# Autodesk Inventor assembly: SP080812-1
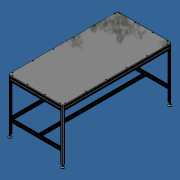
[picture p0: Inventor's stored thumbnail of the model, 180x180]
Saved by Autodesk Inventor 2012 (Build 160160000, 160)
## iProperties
Created: 2012-08
Part Number: SP080812-1
Document SubType Name: Assembly
Designer: Administrator
Author: Administrator
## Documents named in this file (10)
- C:\Andys Backup Data\ANDY'S INVENTOR\INVENTOR LIBRARIES\ASSEMBLY LIBRARY\30 SERIES\TABLES BASES CARTS\SP080812-1 30R90 TABLE\SP080812-1 30R90 TABLE.iam
- C:\Andys Backup Data\ANDY'S INVENTOR\INVENTOR LIBRARIES\ASSEMBLY LIBRARY\30 SERIES\TABLES BASES CARTS\SP080812-1 30R90 TABLE\SP080812-1-1 30R90 LEG.ipt
- C:\Andys Backup Data\ANDY'S INVENTOR\INVENTOR LIBRARIES\PARTS LIBRARY\FEET WHEELS FLOOR FASTENING SUPPORTS\21.1871 LEVELING FOOT M8 45mm BASE.iam
- C:\Andys Backup Data\ANDY'S INVENTOR\INVENTOR LIBRARIES\ASSEMBLY LIBRARY\30 SERIES\TABLES BASES CARTS\SP080812-1 30R90 TABLE\SP080812-1-2 30X60 HORI WIDTH.ipt
- C:\Andys Backup Data\ANDY'S INVENTOR\INVENTOR LIBRARIES\ASSEMBLY LIBRARY\30 SERIES\TABLES BASES CARTS\SP080812-1 30R90 TABLE\SP080812-1-3 30X60 DEPTH HORI.ipt
- C:\Andys Backup Data\ANDY'S INVENTOR\INVENTOR LIBRARIES\ASSEMBLY LIBRARY\30 SERIES\TABLES BASES CARTS\SP080812-1 30R90 TABLE\SP080812-1-4 30X30 DEPTH HORI.ipt
- C:\Andys Backup Data\ANDY'S INVENTOR\INVENTOR LIBRARIES\ASSEMBLY LIBRARY\30 SERIES\TABLES BASES CARTS\SP080812-1 30R90 TABLE\SP080812-1-5 30X30 WIDTH HORI.ipt
- C:\Andys Backup Data\ANDY'S INVENTOR\INVENTOR LIBRARIES\ASSEMBLY LIBRARY\30 SERIES\TABLES BASES CARTS\SP080812-1 30R90 TABLE\SP080812-1-6 TABLE TOP.ipt
- C:\Andys Backup Data\ANDY'S INVENTOR\INVENTOR LIBRARIES\PARTS LIBRARY\30 SERIES\21.1569 M6 SQUARE NUT 30 POS FXG.ipt
- C:\Andys Backup Data\ANDY'S INVENTOR\INVENTOR LIBRARIES\PARTS LIBRARY\FASTENING ELEMENTS\SCREWS COUNTERSUNK\21.1507_9 M6X20 CSUNK BLACK.IPT
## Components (59 placed, 9 different names)
1. SP080812-1-1 30R90 LEG:1 — Insert:1, Flush:2, Flush:3, Flush:7, Flush:8, Flush:17, Flush:18, Mate:8, Mate:10, Mate:14
2. 21.1871 LEVELING FOOT M8 45mm BASE:1 [sub-assembly] — Insert:1
3. SP080812-1-2 30X60 HORI WIDTH:1 — Flush:2, Flush:3, Mate:1, Flush:4, Flush:5, Mate:8
4. SP080812-1-1 30R90 LEG:2 — Mate:1, Flush:4, Flush:5, Insert:2
5. 21.1871 LEVELING FOOT M8 45mm BASE:2 [sub-assembly] — Insert:2
6. SP080812-1-3 30X60 DEPTH HORI:1 — Flush:7, Flush:8, Mate:2, Flush:9, Flush:10, Mate:10, Mate:12, Flush:28
7. SP080812-1-1 30R90 LEG:3 — Mate:2, Flush:9, Flush:10, Mate:3, Flush:11, Flush:12, Insert:4, Flush:22, Flush:23
8. SP080812-1-2 30X60 HORI WIDTH:2 — Mate:3, Flush:11, Flush:12, Mate:4, Flush:13, Flush:14, Mate:9, Flush:26, Mate:11, Flush:27
9. SP080812-1-1 30R90 LEG:4 — Mate:4, Flush:13, Flush:14, Mate:5, Flush:15, Flush:16, Insert:3, Mate:6, Flush:20
10. SP080812-1-3 30X60 DEPTH HORI:2 — Mate:5, Flush:15, Flush:16, Mate:13
11. 21.1871 LEVELING FOOT M8 45mm BASE:3 [sub-assembly] — Insert:3
12. 21.1871 LEVELING FOOT M8 45mm BASE:4 [sub-assembly] — Insert:4, Flush:19
13. SP080812-1-4 30X30 DEPTH HORI:1 — Flush:17, Flush:18, Flush:19, Flush:21, Flush:24, Mate:7, Flush:25
14. SP080812-1-4 30X30 DEPTH HORI:2 — Mate:6, Flush:20, Flush:21
15. SP080812-1-5 30X30 WIDTH HORI:1 — Flush:22, Flush:23, Flush:24
16. SP080812-1-5 30X30 WIDTH HORI:2 — Mate:7, Flush:25, Mate:14
17. SP080812-1-4 30X30 DEPTH HORI:3 — Mate:9, Flush:26, Mate:12
18. SP080812-1-4 30X30 DEPTH HORI:4 — Mate:11, Flush:27, Mate:13
19. SP080812-1-6 TABLE TOP:1 — Flush:28, Insert:5, Insert:6, Insert:7, Insert:8, Insert:9, Insert:10, Insert:11, Insert:12, Insert:13, Insert:14, Insert:15, Insert:16, Insert:17, Insert:18, Insert:19, Insert:20, Insert:21, Insert:22, Insert:23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
20. 21.1507/9 M6x20 C'SUNK BLACK:1 — Insert:8, Mate:53
21. 21.1507/9 M6x20 C'SUNK BLACK:2 — Insert:9, Mate:54
22. 21.1507/9 M6x20 C'SUNK BLACK:3 — Insert:10, Mate:31
23. 21.1507/9 M6x20 C'SUNK BLACK:4 — Insert:11, Mate:29
24. 21.1507/9 M6x20 C'SUNK BLACK:5 — Insert:12, Mate:27
25. 21.1507/9 M6x20 C'SUNK BLACK:6 — Insert:13, Mate:25
26. 21.1507/9 M6x20 C'SUNK BLACK:7 — Insert:14, Mate:23
27. 21.1507/9 M6x20 C'SUNK BLACK:8 — Insert:15, Mate:21
28. 21.1507/9 M6x20 C'SUNK BLACK:9 — Insert:16, Mate:19
29. 21.1507/9 M6x20 C'SUNK BLACK:10 — Insert:17, Mate:17
30. 21.1507/9 M6x20 C'SUNK BLACK:11 — Insert:18, Mate:15
31. 21.1507/9 M6x20 C'SUNK BLACK:12 — Insert:19, Mate:37
32. 21.1507/9 M6x20 C'SUNK BLACK:13 — Insert:21, Mate:41
33. 21.1507/9 M6x20 C'SUNK BLACK:14 — Insert:20, Mate:39
34. 21.1507/9 M6x20 C'SUNK BLACK:15 — Insert:22, Mate:43
35. 21.1507/9 M6x20 C'SUNK BLACK:16 — Insert:23, Mate:36
36. 21.1507/9 M6x20 C'SUNK BLACK:17 — Insert:24, Mate:33
37. 21.1507/9 M6x20 C'SUNK BLACK:18 — Insert:5, Mate:45
38. 21.1507/9 M6x20 C'SUNK BLACK:19 — Insert:6, Mate:47
39. 21.1507/9 M6x20 C'SUNK BLACK:20 — Insert:7, Mate:49
40. 21.1569 M6 SQUARE NUT 30 POS FXG:1 — Mate:35, Mate:36, Angle:7
41. 21.1569 M6 SQUARE NUT 30 POS FXG:2 — Mate:33, Mate:34, Angle:6
42. 21.1569 M6 SQUARE NUT 30 POS FXG:3 — Mate:31, Mate:32
43. 21.1569 M6 SQUARE NUT 30 POS FXG:4 — Mate:29, Mate:30
44. 21.1569 M6 SQUARE NUT 30 POS FXG:5 — Mate:37, Mate:38, Angle:8
45. 21.1569 M6 SQUARE NUT 30 POS FXG:6 — Mate:15, Mate:16, Angle:1
46. 21.1569 M6 SQUARE NUT 30 POS FXG:7 — Mate:47, Mate:48, Angle:13
47. 21.1569 M6 SQUARE NUT 30 POS FXG:8 — Mate:45, Mate:46, Angle:12
48. 21.1569 M6 SQUARE NUT 30 POS FXG:9 — Mate:27, Mate:28
49. 21.1569 M6 SQUARE NUT 30 POS FXG:10 — Mate:43, Mate:44, Angle:11
50. 21.1569 M6 SQUARE NUT 30 POS FXG:11 — Mate:49, Mate:50, Angle:14
51. 21.1569 M6 SQUARE NUT 30 POS FXG:12 — Mate:23, Mate:24, Angle:5
52. 21.1569 M6 SQUARE NUT 30 POS FXG:13 — Mate:41, Mate:42, Angle:10
53. 21.1569 M6 SQUARE NUT 30 POS FXG:14 — Mate:21, Angle:4, Mate:22
54. 21.1569 M6 SQUARE NUT 30 POS FXG:15 — Mate:39, Mate:40, Angle:9
55. 21.1569 M6 SQUARE NUT 30 POS FXG:16 — Mate:25, Mate:26
56. 21.1569 M6 SQUARE NUT 30 POS FXG:17 — Mate:17, Mate:18, Angle:2
57. 21.1569 M6 SQUARE NUT 30 POS FXG:18 — Mate:19, Mate:20, Angle:3
58. 21.1569 M6 SQUARE NUT 30 POS FXG:19 — Mate:51, Mate:53, Angle:15
59. 21.1569 M6 SQUARE NUT 30 POS FXG:20 — Mate:52, Mate:54, Angle:16
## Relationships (120: Mate 54, Flush 26, Insert 24, Angle 16)
- Insert:1: SP080812-1-1 30R90 LEG:1 ↔ 21.1871 LEVELING FOOT M8 45mm BASE:1
- Flush:2: SP080812-1-1 30R90 LEG:1 ↔ SP080812-1-2 30X60 HORI WIDTH:1
- Flush:3: SP080812-1-1 30R90 LEG:1 ↔ SP080812-1-2 30X60 HORI WIDTH:1
- Mate:1: SP080812-1-2 30X60 HORI WIDTH:1 ↔ SP080812-1-1 30R90 LEG:2
- Flush:4: SP080812-1-2 30X60 HORI WIDTH:1 ↔ SP080812-1-1 30R90 LEG:2
- Flush:5: SP080812-1-2 30X60 HORI WIDTH:1 ↔ SP080812-1-1 30R90 LEG:2
- Insert:2: SP080812-1-1 30R90 LEG:2 ↔ 21.1871 LEVELING FOOT M8 45mm BASE:2
- Flush:7: SP080812-1-1 30R90 LEG:1 ↔ SP080812-1-3 30X60 DEPTH HORI:1
- Flush:8: SP080812-1-1 30R90 LEG:1 ↔ SP080812-1-3 30X60 DEPTH HORI:1
- Mate:2: SP080812-1-3 30X60 DEPTH HORI:1 ↔ SP080812-1-1 30R90 LEG:3
- Flush:9: SP080812-1-3 30X60 DEPTH HORI:1 ↔ SP080812-1-1 30R90 LEG:3
- Flush:10: SP080812-1-3 30X60 DEPTH HORI:1 ↔ SP080812-1-1 30R90 LEG:3
- Mate:3: SP080812-1-1 30R90 LEG:3 ↔ SP080812-1-2 30X60 HORI WIDTH:2
- Flush:11: SP080812-1-1 30R90 LEG:3 ↔ SP080812-1-2 30X60 HORI WIDTH:2
- Flush:12: SP080812-1-1 30R90 LEG:3 ↔ SP080812-1-2 30X60 HORI WIDTH:2
- Mate:4: SP080812-1-2 30X60 HORI WIDTH:2 ↔ SP080812-1-1 30R90 LEG:4
- Flush:13: SP080812-1-2 30X60 HORI WIDTH:2 ↔ SP080812-1-1 30R90 LEG:4
- Flush:14: SP080812-1-2 30X60 HORI WIDTH:2 ↔ SP080812-1-1 30R90 LEG:4
- Mate:5: SP080812-1-1 30R90 LEG:4 ↔ SP080812-1-3 30X60 DEPTH HORI:2
- Flush:15: SP080812-1-1 30R90 LEG:4 ↔ SP080812-1-3 30X60 DEPTH HORI:2
- Flush:16: SP080812-1-1 30R90 LEG:4 ↔ SP080812-1-3 30X60 DEPTH HORI:2
- Insert:3: SP080812-1-1 30R90 LEG:4 ↔ 21.1871 LEVELING FOOT M8 45mm BASE:3
- Insert:4: SP080812-1-1 30R90 LEG:3 ↔ 21.1871 LEVELING FOOT M8 45mm BASE:4
- Flush:17: SP080812-1-1 30R90 LEG:1 ↔ SP080812-1-4 30X30 DEPTH HORI:1
- Flush:18: SP080812-1-1 30R90 LEG:1 ↔ SP080812-1-4 30X30 DEPTH HORI:1
- Flush:19: 21.1871 LEVELING FOOT M8 45mm BASE:4 ↔ SP080812-1-4 30X30 DEPTH HORI:1
- Mate:6: SP080812-1-1 30R90 LEG:4 ↔ SP080812-1-4 30X30 DEPTH HORI:2
- Flush:20: SP080812-1-1 30R90 LEG:4 ↔ SP080812-1-4 30X30 DEPTH HORI:2
- Flush:21: SP080812-1-4 30X30 DEPTH HORI:1 ↔ SP080812-1-4 30X30 DEPTH HORI:2
- Flush:22: SP080812-1-1 30R90 LEG:3 ↔ SP080812-1-5 30X30 WIDTH HORI:1
- Flush:23: SP080812-1-1 30R90 LEG:3 ↔ SP080812-1-5 30X30 WIDTH HORI:1
- Flush:24: SP080812-1-4 30X30 DEPTH HORI:1 ↔ SP080812-1-5 30X30 WIDTH HORI:1
- Mate:7: SP080812-1-4 30X30 DEPTH HORI:1 ↔ SP080812-1-5 30X30 WIDTH HORI:2
- Flush:25: SP080812-1-4 30X30 DEPTH HORI:1 ↔ SP080812-1-5 30X30 WIDTH HORI:2
- Mate:8: SP080812-1-1 30R90 LEG:1 ↔ SP080812-1-2 30X60 HORI WIDTH:1
- Mate:9: SP080812-1-2 30X60 HORI WIDTH:2 ↔ SP080812-1-4 30X30 DEPTH HORI:3
- Flush:26: SP080812-1-2 30X60 HORI WIDTH:2 ↔ SP080812-1-4 30X30 DEPTH HORI:3
- Mate:10: SP080812-1-1 30R90 LEG:1 ↔ SP080812-1-3 30X60 DEPTH HORI:1
- Mate:11: SP080812-1-2 30X60 HORI WIDTH:2 ↔ SP080812-1-4 30X30 DEPTH HORI:4
- Flush:27: SP080812-1-2 30X60 HORI WIDTH:2 ↔ SP080812-1-4 30X30 DEPTH HORI:4
- Mate:12: SP080812-1-3 30X60 DEPTH HORI:1 ↔ SP080812-1-4 30X30 DEPTH HORI:3
- Mate:13: SP080812-1-3 30X60 DEPTH HORI:2 ↔ SP080812-1-4 30X30 DEPTH HORI:4
- Mate:14: SP080812-1-1 30R90 LEG:1 ↔ SP080812-1-5 30X30 WIDTH HORI:2
- Flush:28: SP080812-1-3 30X60 DEPTH HORI:1 ↔ SP080812-1-6 TABLE TOP:1
- Insert:5: SP080812-1-6 TABLE TOP:1 ↔ 21.1507/9 M6x20 C'SUNK BLACK:18
- Insert:6: SP080812-1-6 TABLE TOP:1 ↔ 21.1507/9 M6x20 C'SUNK BLACK:19
- Insert:7: SP080812-1-6 TABLE TOP:1 ↔ 21.1507/9 M6x20 C'SUNK BLACK:20
- Insert:8: SP080812-1-6 TABLE TOP:1 ↔ 21.1507/9 M6x20 C'SUNK BLACK:1
- Insert:9: SP080812-1-6 TABLE TOP:1 ↔ 21.1507/9 M6x20 C'SUNK BLACK:2
- Insert:10: SP080812-1-6 TABLE TOP:1 ↔ 21.1507/9 M6x20 C'SUNK BLACK:3
- Insert:11: SP080812-1-6 TABLE TOP:1 ↔ 21.1507/9 M6x20 C'SUNK BLACK:4
- Insert:12: SP080812-1-6 TABLE TOP:1 ↔ 21.1507/9 M6x20 C'SUNK BLACK:5
- Insert:13: SP080812-1-6 TABLE TOP:1 ↔ 21.1507/9 M6x20 C'SUNK BLACK:6
- Insert:14: SP080812-1-6 TABLE TOP:1 ↔ 21.1507/9 M6x20 C'SUNK BLACK:7
- Insert:15: SP080812-1-6 TABLE TOP:1 ↔ 21.1507/9 M6x20 C'SUNK BLACK:8
- Insert:16: SP080812-1-6 TABLE TOP:1 ↔ 21.1507/9 M6x20 C'SUNK BLACK:9
- Insert:17: SP080812-1-6 TABLE TOP:1 ↔ 21.1507/9 M6x20 C'SUNK BLACK:10
- Insert:18: SP080812-1-6 TABLE TOP:1 ↔ 21.1507/9 M6x20 C'SUNK BLACK:11
- Insert:19: SP080812-1-6 TABLE TOP:1 ↔ 21.1507/9 M6x20 C'SUNK BLACK:12
- Insert:20: SP080812-1-6 TABLE TOP:1 ↔ 21.1507/9 M6x20 C'SUNK BLACK:14
- Insert:21: SP080812-1-6 TABLE TOP:1 ↔ 21.1507/9 M6x20 C'SUNK BLACK:13
- Insert:22: SP080812-1-6 TABLE TOP:1 ↔ 21.1507/9 M6x20 C'SUNK BLACK:15
- Insert:23: SP080812-1-6 TABLE TOP:1 ↔ 21.1507/9 M6x20 C'SUNK BLACK:16
- Insert:24: SP080812-1-6 TABLE TOP:1 ↔ 21.1507/9 M6x20 C'SUNK BLACK:17
- Mate:15: 21.1507/9 M6x20 C'SUNK BLACK:11 ↔ 21.1569 M6 SQUARE NUT 30 POS FXG:6
- Mate:16: SP080812-1-6 TABLE TOP:1 ↔ 21.1569 M6 SQUARE NUT 30 POS FXG:6
- Angle:1: SP080812-1-6 TABLE TOP:1 ↔ 21.1569 M6 SQUARE NUT 30 POS FXG:6
- Mate:17: 21.1507/9 M6x20 C'SUNK BLACK:10 ↔ 21.1569 M6 SQUARE NUT 30 POS FXG:17
- Mate:18: SP080812-1-6 TABLE TOP:1 ↔ 21.1569 M6 SQUARE NUT 30 POS FXG:17
- Angle:2: SP080812-1-6 TABLE TOP:1 ↔ 21.1569 M6 SQUARE NUT 30 POS FXG:17
- Mate:19: 21.1507/9 M6x20 C'SUNK BLACK:9 ↔ 21.1569 M6 SQUARE NUT 30 POS FXG:18
- Mate:20: SP080812-1-6 TABLE TOP:1 ↔ 21.1569 M6 SQUARE NUT 30 POS FXG:18
- Angle:3: SP080812-1-6 TABLE TOP:1 ↔ 21.1569 M6 SQUARE NUT 30 POS FXG:18
- Mate:21: 21.1507/9 M6x20 C'SUNK BLACK:8 ↔ 21.1569 M6 SQUARE NUT 30 POS FXG:14
- Angle:4: SP080812-1-6 TABLE TOP:1 ↔ 21.1569 M6 SQUARE NUT 30 POS FXG:14
- Mate:22: SP080812-1-6 TABLE TOP:1 ↔ 21.1569 M6 SQUARE NUT 30 POS FXG:14
- Mate:23: 21.1507/9 M6x20 C'SUNK BLACK:7 ↔ 21.1569 M6 SQUARE NUT 30 POS FXG:12
- Mate:24: SP080812-1-6 TABLE TOP:1 ↔ 21.1569 M6 SQUARE NUT 30 POS FXG:12
- Angle:5: SP080812-1-6 TABLE TOP:1 ↔ 21.1569 M6 SQUARE NUT 30 POS FXG:12
- Mate:25: 21.1507/9 M6x20 C'SUNK BLACK:6 ↔ 21.1569 M6 SQUARE NUT 30 POS FXG:16
- Mate:26: SP080812-1-6 TABLE TOP:1 ↔ 21.1569 M6 SQUARE NUT 30 POS FXG:16
- Mate:27: 21.1507/9 M6x20 C'SUNK BLACK:5 ↔ 21.1569 M6 SQUARE NUT 30 POS FXG:9
- Mate:28: SP080812-1-6 TABLE TOP:1 ↔ 21.1569 M6 SQUARE NUT 30 POS FXG:9
- Mate:29: 21.1507/9 M6x20 C'SUNK BLACK:4 ↔ 21.1569 M6 SQUARE NUT 30 POS FXG:4
- Mate:30: SP080812-1-6 TABLE TOP:1 ↔ 21.1569 M6 SQUARE NUT 30 POS FXG:4
- Mate:31: 21.1507/9 M6x20 C'SUNK BLACK:3 ↔ 21.1569 M6 SQUARE NUT 30 POS FXG:3
- Mate:32: SP080812-1-6 TABLE TOP:1 ↔ 21.1569 M6 SQUARE NUT 30 POS FXG:3
- Mate:33: 21.1507/9 M6x20 C'SUNK BLACK:17 ↔ 21.1569 M6 SQUARE NUT 30 POS FXG:2
- Mate:34: SP080812-1-6 TABLE TOP:1 ↔ 21.1569 M6 SQUARE NUT 30 POS FXG:2
- Angle:6: SP080812-1-6 TABLE TOP:1 ↔ 21.1569 M6 SQUARE NUT 30 POS FXG:2
- Mate:35: SP080812-1-6 TABLE TOP:1 ↔ 21.1569 M6 SQUARE NUT 30 POS FXG:1
- Mate:36: 21.1507/9 M6x20 C'SUNK BLACK:16 ↔ 21.1569 M6 SQUARE NUT 30 POS FXG:1
- Angle:7: SP080812-1-6 TABLE TOP:1 ↔ 21.1569 M6 SQUARE NUT 30 POS FXG:1
- Mate:37: 21.1507/9 M6x20 C'SUNK BLACK:12 ↔ 21.1569 M6 SQUARE NUT 30 POS FXG:5
- Mate:38: SP080812-1-6 TABLE TOP:1 ↔ 21.1569 M6 SQUARE NUT 30 POS FXG:5
- Angle:8: SP080812-1-6 TABLE TOP:1 ↔ 21.1569 M6 SQUARE NUT 30 POS FXG:5
- Mate:39: 21.1507/9 M6x20 C'SUNK BLACK:14 ↔ 21.1569 M6 SQUARE NUT 30 POS FXG:15
- Mate:40: SP080812-1-6 TABLE TOP:1 ↔ 21.1569 M6 SQUARE NUT 30 POS FXG:15
- Angle:9: SP080812-1-6 TABLE TOP:1 ↔ 21.1569 M6 SQUARE NUT 30 POS FXG:15
- Mate:41: 21.1507/9 M6x20 C'SUNK BLACK:13 ↔ 21.1569 M6 SQUARE NUT 30 POS FXG:13
- Mate:42: SP080812-1-6 TABLE TOP:1 ↔ 21.1569 M6 SQUARE NUT 30 POS FXG:13
- Angle:10: SP080812-1-6 TABLE TOP:1 ↔ 21.1569 M6 SQUARE NUT 30 POS FXG:13
- Mate:43: 21.1507/9 M6x20 C'SUNK BLACK:15 ↔ 21.1569 M6 SQUARE NUT 30 POS FXG:10
- Mate:44: SP080812-1-6 TABLE TOP:1 ↔ 21.1569 M6 SQUARE NUT 30 POS FXG:10
- Angle:11: SP080812-1-6 TABLE TOP:1 ↔ 21.1569 M6 SQUARE NUT 30 POS FXG:10
- Mate:45: 21.1507/9 M6x20 C'SUNK BLACK:18 ↔ 21.1569 M6 SQUARE NUT 30 POS FXG:8
- Mate:46: SP080812-1-6 TABLE TOP:1 ↔ 21.1569 M6 SQUARE NUT 30 POS FXG:8
- Angle:12: SP080812-1-6 TABLE TOP:1 ↔ 21.1569 M6 SQUARE NUT 30 POS FXG:8
- Mate:47: 21.1507/9 M6x20 C'SUNK BLACK:19 ↔ 21.1569 M6 SQUARE NUT 30 POS FXG:7
- Mate:48: SP080812-1-6 TABLE TOP:1 ↔ 21.1569 M6 SQUARE NUT 30 POS FXG:7
- Angle:13: SP080812-1-6 TABLE TOP:1 ↔ 21.1569 M6 SQUARE NUT 30 POS FXG:7
- Mate:49: 21.1507/9 M6x20 C'SUNK BLACK:20 ↔ 21.1569 M6 SQUARE NUT 30 POS FXG:11
- Mate:50: SP080812-1-6 TABLE TOP:1 ↔ 21.1569 M6 SQUARE NUT 30 POS FXG:11
- Angle:14: SP080812-1-6 TABLE TOP:1 ↔ 21.1569 M6 SQUARE NUT 30 POS FXG:11
- Mate:51: SP080812-1-6 TABLE TOP:1 ↔ 21.1569 M6 SQUARE NUT 30 POS FXG:19
- Mate:52: SP080812-1-6 TABLE TOP:1 ↔ 21.1569 M6 SQUARE NUT 30 POS FXG:20
- Mate:53: 21.1507/9 M6x20 C'SUNK BLACK:1 ↔ 21.1569 M6 SQUARE NUT 30 POS FXG:19
- Angle:15: SP080812-1-6 TABLE TOP:1 ↔ 21.1569 M6 SQUARE NUT 30 POS FXG:19
- Mate:54: 21.1507/9 M6x20 C'SUNK BLACK:2 ↔ 21.1569 M6 SQUARE NUT 30 POS FXG:20
- Angle:16: SP080812-1-6 TABLE TOP:1 ↔ 21.1569 M6 SQUARE NUT 30 POS FXG:20
